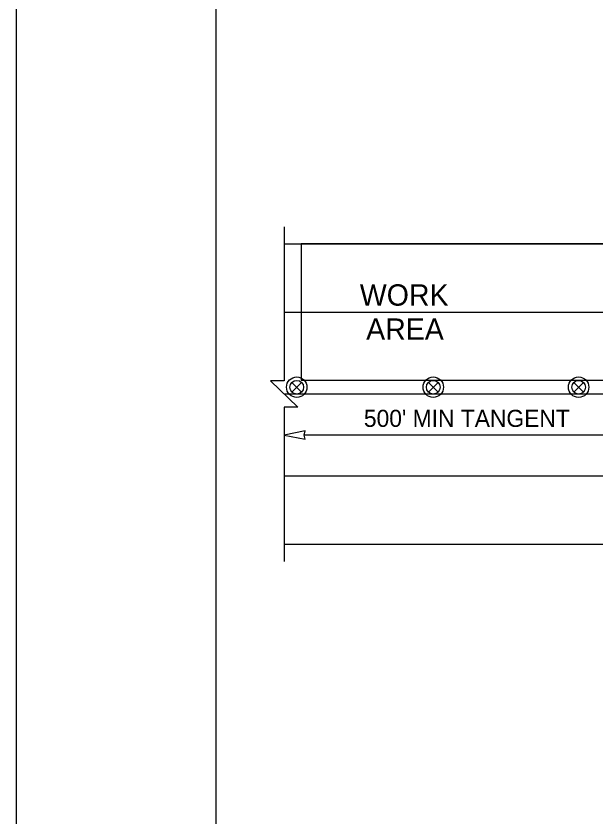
# Model space of a CAD drawing. Extents: x 99999 to 100116, y 99995 to 100013.
# Drawn here: x 100059.062 to 100061.782, y 100005.282 to 100009.035 of the extents above; entities that cross this region are included whole.
import ezdxf

# ---------------------------------------------------------------- set-up
doc = ezdxf.new("R2010")
doc.units = 0
for name, color, linetype in [('RD_MK_LineEdgeYellow', 7, 'Continuous'), ('RD_MK_LineLane', 7, 'Continuous'), ('SH_GI_PlotLimits', 7, 'Continuous'), ('SH_GI_SheetBorder', 7, 'Continuous'), ('TR_WZ_TrafficSafetyDrum', 7, 'Continuous'), ('TR_WZ_WorkAreaLabel', 7, 'Continuous'), ('TR_WZ_WorkZoneDetails', 7, 'Continuous'), ('TR_WZ_WorkZoneTextCurrent', 7, 'Continuous')]:
    doc.layers.add(name, color=color, linetype=linetype)

msp = doc.modelspace()

# ---------------------------------------------------------------- linework, layer by layer
at = {"layer": 'RD_MK_LineEdgeYellow'}
for p, q in [((100060.32, 100007.648), (100062.7119, 100007.648)), ((100060.32, 100006.88), (100067.555, 100006.88))]:
    msp.add_line(p, q, dxfattribs=at)
at = {"layer": 'RD_MK_LineLane'}
msp.add_lwpolyline([(100067.555, 100007.264), (100060.32, 100007.264)], dxfattribs=at)
at = {"layer": 'SH_GI_PlotLimits'}
msp.add_lwpolyline([(100059.0625, 99999.6875), (100076.0625, 99999.6875), (100076.0625, 100010.6875), (100059.0625, 100010.6875)], close=True, dxfattribs=at)
at = {"layer": 'SH_GI_SheetBorder'}
msp.add_line((100060, 100010.375), (100060, 100000), dxfattribs=at)
at = {"layer": 'TR_WZ_TrafficSafetyDrum'}
for p, q in [((100060.3563, 100007.2734), (100060.4015, 100007.3186)), ((100060.4015, 100007.2734), (100060.3563, 100007.3186)), ((100060.9963, 100007.2734), (100061.0415, 100007.3186)), ((100061.0415, 100007.2734), (100060.9963, 100007.3186)), ((100061.6779, 100007.2734), (100061.7232, 100007.3186)), ((100061.7232, 100007.2734), (100061.6779, 100007.3186))]:
    msp.add_line(p, q, dxfattribs=at)
for centre, radius in [((100060.3789, 100007.296), 0.048), ((100060.3789, 100007.296), 0.048), ((100061.0189, 100007.296), 0.048), ((100061.0189, 100007.296), 0.048), ((100061.7006, 100007.296), 0.048), ((100061.7006, 100007.296), 0.048), ((100060.3789, 100007.296), 0.032), ((100061.0189, 100007.296), 0.032), ((100061.7006, 100007.296), 0.032)]:
    msp.add_circle(centre, radius, dxfattribs=at)
at = {"layer": 'TR_WZ_WorkZoneDetails'}
for p, q in [((100060.32, 100007.968), (100062.9559, 100007.968)), ((100061.9918, 100007.072), (100060.4137, 100007.072)), ((100060.32, 100006.56), (100067.555, 100006.56))]:
    msp.add_line(p, q, dxfattribs=at)
msp.add_lwpolyline([(100060.32, 100008.048), (100060.32, 100007.326), (100060.256, 100007.326), (100060.384, 100007.2021), (100060.32, 100007.2021), (100060.32, 100006.48)], dxfattribs=at)
for points in [[(100060.4, 100007.968), (100060.4, 100007.3291), (100062.0856, 100007.3291), (100062.0856, 100007.968)], [(100060.32, 100007.072), (100060.4183, 100007.0528), (100060.4137, 100007.072), (100060.4183, 100007.0913)]]:
    msp.add_lwpolyline(points, close=True, dxfattribs=at)

# ---------------------------------------------------------------- texts
at = {"layer": 'TR_WZ_WorkAreaLabel'}
for s, p in [('WORK', (100060.6746, 100007.678)), ('AREA', (100060.7043, 100007.518))]:
    msp.add_text(s, height=0.1, dxfattribs=at).set_placement(p)
at = {"layer": 'TR_WZ_WorkZoneTextCurrent'}
msp.add_text("500' MIN TANGENT", height=0.08, dxfattribs=at).set_placement((100060.6937, 100007.11))

doc.saveas('drawing.dxf')
